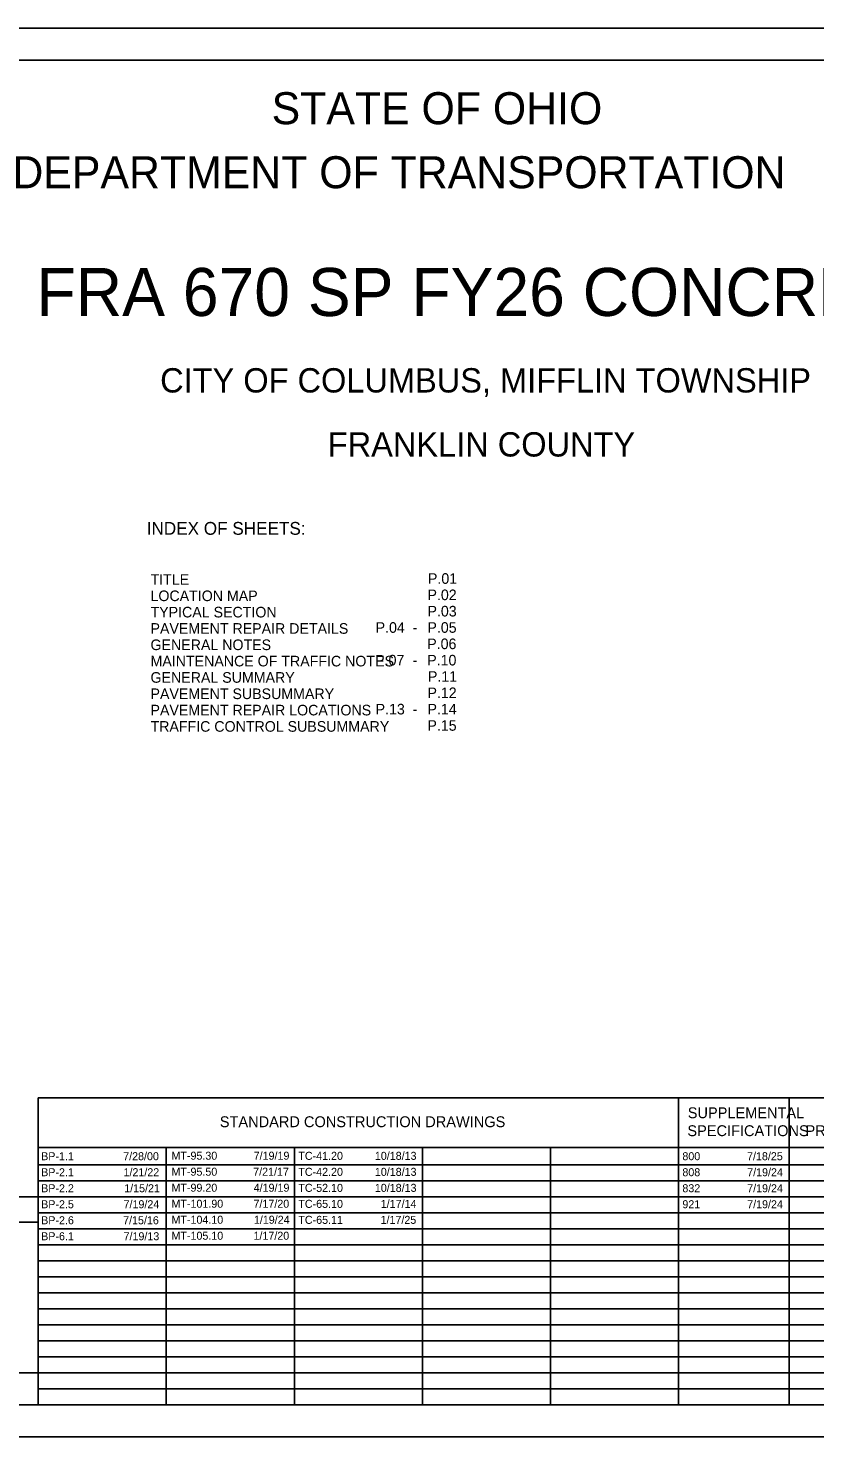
# Model space of a CAD drawing. Extents: x 0 to 34, y 0 to 22.
# Drawn here: x 9.99 to 22.28, y 0 to 22 of the extents above; entities that cross this region are included whole.
import ezdxf

# ---------------------------------------------------------------- set-up
doc = ezdxf.new("R2010")
doc.units = 0
for name, color, linetype in [('Default', 7, 'Continuous'), ('SH_Border', 7, 'Continuous'), ('SH_Cut_Line', 7, 'Continuous'), ('SH_Data', 7, 'Continuous'), ('SH_Text', 7, 'Continuous')]:
    doc.layers.add(name, color=color, linetype=linetype)

msp = doc.modelspace()

# ---------------------------------------------------------------- linework, layer by layer
at = {"layer": 'SH_Border'}
msp.add_lwpolyline([(1.5, 21.5), (33.5, 21.5), (33.5, 0.5), (1.5, 0.5)], close=True, dxfattribs=at)
at = {"layer": 'SH_Cut_Line'}
msp.add_lwpolyline([(0, 0), (34, 0), (34, 22), (0, 22)], close=True, dxfattribs=at)
at = {"layer": 'SH_Data'}
for p, q in [((10.15, 5.292), (23.6, 5.292)), ((10.15, 0.5), (10.15, 5.292)), ((20.15, 0.5), (20.15, 5.292)), ((21.875, 0.5), (21.875, 5.292)), ((10.15, 4.521), (23.6, 4.521)), ((12.15, 0.5), (12.15, 4.521)), ((14.15, 0.5), (14.15, 4.521)), ((16.15, 0.5), (16.15, 4.521)), ((18.15, 0.5), (18.15, 4.521)), ((10.15, 4.25), (23.6, 4.25)), ((10.15, 4), (23.6, 4)), ((10.15, 3.75), (7.35, 3.75)), ((10.15, 3.75), (23.6, 3.75)), ((10.15, 0.5), (10.15, 3.75)), ((10.15, 3.35), (7.35, 3.35)), ((10.15, 3.5), (23.6, 3.5)), ((10.15, 3.25), (23.6, 3.25)), ((10.15, 3), (23.6, 3)), ((10.15, 2.75), (23.6, 2.75)), ((10.15, 2.5), (23.6, 2.5)), ((10.15, 2.25), (23.6, 2.25)), ((10.15, 2), (23.6, 2)), ((10.15, 1.75), (23.6, 1.75)), ((10.15, 1.5), (23.6, 1.5)), ((10.15, 1.25), (23.6, 1.25)), ((10.15, 1), (23.6, 1)), ((10.15, 0.75), (23.6, 0.75)), ((10.15, 0.5), (7.35, 0.5))]:
    msp.add_line(p, q, dxfattribs=at)
msp.add_lwpolyline([(10.15, 0.5), (10.15, 1), (7.35, 1), (7.35, 0.5)], close=True, dxfattribs=at)

# ---------------------------------------------------------------- texts
at = {"layer": 'Default'}
for s, height, p in [('TITLE', 0.1656, (11.904, 13.307)), ('P.01', 0.1656, (16.236, 13.322)), ('LOCATION MAP', 0.1656, (11.904, 13.052)), ('P.02', 0.1656, (16.229, 13.067)), ('P.03', 0.1656, (16.229, 12.812)), ('TYPICAL SECTION', 0.1656, (11.904, 12.797)), ('PAVEMENT REPAIR DETAILS', 0.1656, (11.904, 12.542)), ('P.04', 0.1656, (15.419, 12.557)), ('-', 0.166, (15.997, 12.557)), ('P.05', 0.1656, (16.228, 12.557)), ('GENERAL NOTES', 0.1656, (11.904, 12.287)), ('P.06', 0.1656, (16.225, 12.302)), ('MAINTENANCE OF TRAFFIC NOTES', 0.1656, (11.904, 12.032)), ('P.07', 0.1656, (15.412, 12.047)), ('-', 0.166, (15.997, 12.047)), ('P.10', 0.1656, (16.225, 12.047)), ('GENERAL SUMMARY', 0.1656, (11.904, 11.777)), ('P.11', 0.1656, (16.236, 11.792)), ('PAVEMENT SUBSUMMARY', 0.1656, (11.904, 11.522)), ('P.12', 0.1656, (16.229, 11.537)), ('P.13', 0.1656, (15.419, 11.282)), ('P.14', 0.1656, (16.229, 11.282)), ('PAVEMENT REPAIR LOCATIONS', 0.1656, (11.904, 11.267)), ('-', 0.166, (15.997, 11.282)), ('TRAFFIC CONTROL SUBSUMMARY', 0.1656, (11.904, 11.012)), ('P.15', 0.1656, (16.228, 11.027)), ('BP-1.1', 0.125, (10.196, 4.32)), ('7/28/00', 0.125, (11.477, 4.32)), ('MT-95.30', 0.125, (12.231, 4.328)), ('7/19/19', 0.125, (13.515, 4.328)), ('TC-41.20', 0.125, (14.212, 4.326)), ('10/18/13', 0.125, (15.407, 4.326)), ('800', 0.125, (20.209, 4.32)), ('7/18/25', 0.125, (21.219, 4.32)), ('BP-2.1', 0.125, (10.196, 4.07)), ('1/21/22', 0.125, (11.482, 4.07)), ('MT-95.50', 0.125, (12.231, 4.078)), ('7/21/17', 0.125, (13.507, 4.078)), ('TC-42.20', 0.125, (14.212, 4.076)), ('10/18/13', 0.125, (15.407, 4.076)), ('808', 0.125, (20.209, 4.07)), ('7/19/24', 0.125, (21.221, 4.07)), ('BP-2.2', 0.125, (10.196, 3.82)), ('1/15/21', 0.125, (11.493, 3.82)), ('MT-99.20', 0.125, (12.231, 3.828)), ('4/19/19', 0.125, (13.515, 3.828)), ('TC-52.10', 0.125, (14.212, 3.826)), ('10/18/13', 0.125, (15.407, 3.826)), ('832', 0.125, (20.209, 3.82)), ('7/19/24', 0.125, (21.221, 3.82)), ('BP-2.5', 0.125, (10.196, 3.57)), ('7/19/24', 0.125, (11.483, 3.57)), ('MT-101.90', 0.125, (12.231, 3.578)), ('7/17/20', 0.125, (13.512, 3.578)), ('TC-65.10', 0.125, (14.212, 3.576)), ('1/17/14', 0.125, (15.499, 3.576)), ('921', 0.125, (20.209, 3.57)), ('7/19/24', 0.125, (21.221, 3.57)), ('BP-2.6', 0.125, (10.196, 3.32)), ('7/15/16', 0.125, (11.476, 3.32)), ('MT-104.10', 0.125, (12.231, 3.328)), ('1/19/24', 0.125, (13.518, 3.328)), ('TC-65.11', 0.125, (14.212, 3.326)), ('1/17/25', 0.125, (15.496, 3.326)), ('BP-6.1', 0.125, (10.196, 3.07)), ('7/19/13', 0.125, (11.483, 3.07)), ('MT-105.10', 0.125, (12.231, 3.078)), ('1/17/20', 0.125, (13.512, 3.078))]:
    msp.add_text(s, height=height, dxfattribs=at).set_placement(p)
at = {"layer": 'SH_Text'}
for s, height, p in [('STATE OF OHIO', 0.5, (13.795, 20.5)), ('DEPARTMENT OF TRANSPORTATION', 0.5, (9.747, 19.5)), ('FRA 670 SP FY26 CONCRETE', 0.75, (10.124, 17.505)), ('CITY OF COLUMBUS, MIFFLIN TOWNSHIP', 0.38, (12.054, 16.31)), ('FRANKLIN COUNTY', 0.38, (14.672, 15.31)), ('INDEX OF SHEETS:', 0.2, (11.844, 14.088)), ('SUPPLEMENTAL', 0.17, (20.293, 4.976)), ('STANDARD CONSTRUCTION DRAWINGS', 0.17, (12.986, 4.836)), ('SPECIFICATIONS', 0.17, (20.287, 4.696)), ('PROVISIONS', 0.17, (22.132, 4.696))]:
    msp.add_text(s, height=height, dxfattribs=at).set_placement(p)

doc.saveas('drawing.dxf')
